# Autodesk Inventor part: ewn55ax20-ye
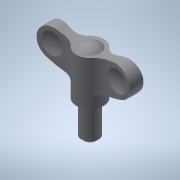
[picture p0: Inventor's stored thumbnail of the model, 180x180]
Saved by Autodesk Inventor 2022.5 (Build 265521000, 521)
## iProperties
Created: 2016-12
Part Number: ewn55ax20-ye
Material: 一般
Document SubType Name: Modeling
Designer: imaocorp
Density: 1 g/cm^3
Appearance: 既定
Author: imaocorp
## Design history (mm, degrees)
node "ewn55ax20-ye.x_t1"
node "ewn55ax20-ye"
node "Base1"
